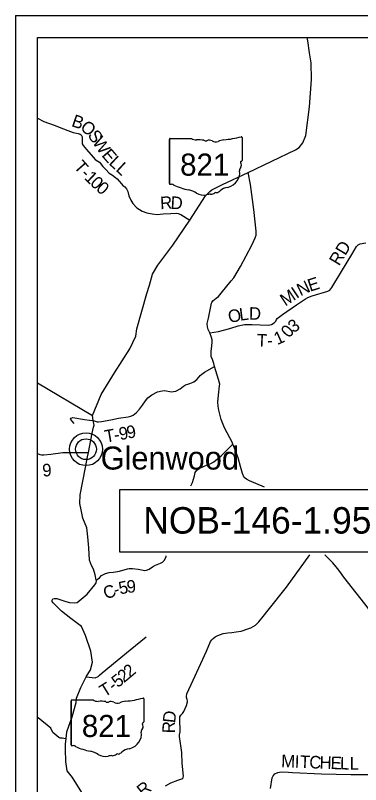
# Model space of a CAD drawing. Extents: x -15 to 405, y -40 to 87.
# Drawn here: x -7.868 to -6.302, y 17.574 to 21.058 of the extents above; entities that cross this region are included whole.
import ezdxf

# ---------------------------------------------------------------- set-up
doc = ezdxf.new("R2010")
doc.units = 0
for name, color, linetype in [('GM_P_State_Location', 7, 'Continuous'), ('GM_X_Adjacent_County', 7, 'Continuous'), ('GM_X_Major_Lake_Text', 7, 'Continuous'), ('GM_X_Minor_Lake', 7, 'Continuous'), ('GM_X_Minor_River', 7, 'Continuous'), ('GM_X_Township', 7, 'Continuous'), ('GM_X_Township_ROW', 7, 'Continuous'), ('GM_X_Township_Subdivision', 7, 'Continuous'), ('GM_X_Township_Subdivision_Text', 7, 'Continuous'), ('GM_X_Township_Text', 7, 'Continuous'), ('GM_X_Unincorporated_Location', 7, 'Continuous')]:
    doc.layers.add(name, color=color, linetype=linetype)

msp = doc.modelspace()

# ---------------------------------------------------------------- linework, layer by layer
at = {"layer": 'GM_P_State_Location'}
for points in [[(-7.6453, 20.5423), (-7.6416, 20.5409), (-7.6058, 20.5284), (-7.5836, 20.5229), (-7.5738, 20.5197), (-7.5689, 20.517), (-7.5648, 20.5087), (-7.5643, 20.4848), (-7.5644, 20.4764), (-7.5603, 20.4692), (-7.5457, 20.4505), (-7.5155, 20.4153), (-7.5057, 20.4057), (-7.4937, 20.398), (-7.487, 20.3934), (-7.481, 20.3873), (-7.4716, 20.3743), (-7.4574, 20.3594), (-7.4421, 20.3437), (-7.4278, 20.3341), (-7.4132, 20.3245), (-7.4064, 20.3183), (-7.3971, 20.3076), (-7.3866, 20.295), (-7.3799, 20.2881), (-7.3709, 20.2809), (-7.3642, 20.2721), (-7.3583, 20.2599), (-7.3528, 20.2412), (-7.3435, 20.2211), (-7.3357, 20.2062), (-7.3167, 20.1871), (-7.293, 20.1721), (-7.2723, 20.1639), (-7.2481, 20.1587), (-7.224, 20.157), (-7.1979, 20.159), (-7.1627, 20.1602), (-7.137, 20.1618), (-7.1294, 20.161), (-7.1177, 20.1567), (-7.0772, 20.1302)], [(-6.9855, 19.6208), (-6.947, 19.6268), (-6.8954, 19.6405), (-6.8575, 19.6512), (-6.8287, 19.6573), (-6.8166, 19.6584), (-6.7939, 19.6585), (-6.7217, 19.6548), (-6.7062, 19.6584), (-6.6933, 19.6659), (-6.6868, 19.6734), (-6.684, 19.6802), (-6.6802, 19.6855), (-6.6684, 19.6941), (-6.6554, 19.7038), (-6.5926, 19.7464), (-6.5519, 19.7741), (-6.5413, 19.7801), (-6.5208, 19.7871), (-6.4506, 19.8091), (-6.4415, 19.8132), (-6.4323, 19.8249), (-6.3881, 19.898), (-6.3412, 19.9756), (-6.3204, 20.0107), (-6.3136, 20.0186), (-6.3033, 20.023), (-6.2775, 20.0285)], [(-7.5144, 19.2228), (-7.4968, 19.2174), (-7.4912, 19.2175), (-7.4775, 19.2183), (-7.4348, 19.2262), (-7.3997, 19.2333), (-7.3558, 19.2401), (-7.3448, 19.2421), (-7.3339, 19.2468), (-7.3177, 19.2598), (-7.3045, 19.2743), (-7.291, 19.2919), (-7.2779, 19.3128), (-7.2667, 19.3262), (-7.2486, 19.3392), (-7.2229, 19.3523), (-7.2014, 19.3582), (-7.1916, 19.359), (-7.1601, 19.3536), (-7.1506, 19.354), (-7.1393, 19.3556), (-7.1208, 19.3668), (-7.105, 19.3783), (-7.0959, 19.3841), (-7.0857, 19.3872), (-7.0718, 19.3922), (-7.0586, 19.398), (-7.0442, 19.4084), (-7.0345, 19.4206), (-7.0289, 19.4274), (-7.0228, 19.4332), (-7.0093, 19.4416), (-6.9644, 19.4682)], [(-7.6014, 19.2096), (-7.6174, 19.2293), (-7.6141, 19.2334), (-7.6075, 19.2363), (-7.5538, 19.228), (-7.5321, 19.2252), (-7.5144, 19.2228)], [(-7.7679, 19.0738), (-7.7563, 19.0694), (-7.7495, 19.0675), (-7.7381, 19.0672), (-7.7075, 19.0701), (-7.6522, 19.0785), (-7.6231, 19.0787), (-7.5369, 19.0787)], [(-7.1873, 17.5685), (-7.1632, 17.5812), (-7.1311, 17.5944), (-7.113, 17.6006), (-7.1088, 17.6025), (-7.1062, 17.6052), (-7.1055, 17.6113), (-7.1112, 17.6712), (-7.1134, 17.7189), (-7.123, 17.7909), (-7.1234, 17.7993), (-7.1209, 17.8129), (-7.1202, 17.8243), (-7.1212, 17.86), (-7.1221, 17.8763), (-7.1214, 17.8812), (-7.1173, 17.8884), (-7.1101, 17.8957), (-7.1041, 17.9049), (-7.0918, 17.9319), (-7.0874, 17.9482), (-7.0874, 17.9528), (-7.089, 17.9588), (-7.0921, 17.9679), (-7.0921, 17.9732), (-7.0903, 17.9842), (-7.0608, 18.0467), (-7.0012, 18.1784), (-6.9825, 18.2214), (-6.9773, 18.2294), (-6.9713, 18.2363), (-6.9615, 18.2435), (-6.9494, 18.2493), (-6.9252, 18.2586), (-6.9044, 18.2618), (-6.8863, 18.2631), (-6.867, 18.2652), (-6.8439, 18.2688), (-6.8133, 18.2789), (-6.7994, 18.2843), (-6.779, 18.2966), (-6.7628, 18.3107), (-6.7433, 18.3359), (-6.7208, 18.3638), (-6.6378, 18.4684), (-6.5326, 18.6142)], [(-7.4864, 18.0688), (-7.4748, 18.0793), (-7.4064, 18.1358), (-7.3467, 18.184), (-7.2747, 18.2424)], [(-7.5461, 18.0614), (-7.5056, 18.0576), (-7.4923, 18.0634), (-7.4864, 18.0688)], [(-7.6378, 17.7811), (-7.6483, 17.7829), (-7.6545, 17.7835), (-7.6644, 17.7848), (-7.6708, 17.7877), (-7.6986, 17.8103), (-7.7063, 17.8292), (-7.764, 17.8757), (-7.7679, 17.8783)], [(-6.7106, 17.556), (-6.703, 17.6042), (-6.6985, 17.6141), (-6.6902, 17.6226), (-6.6774, 17.628), (-6.6615, 17.6311), (-6.6289, 17.6299), (-6.6107, 17.6289), (-6.4793, 17.6231), (-6.3457, 17.6188), (-6.2389, 17.6197), (-6.2279, 17.6205), (-6.2151, 17.6225), (-6.2026, 17.6207), (-6.1847, 17.6159), (-6.1404, 17.608), (-6.09, 17.6095)]]:
    msp.add_lwpolyline(points, dxfattribs=at)
at = {"layer": 'GM_X_Adjacent_County'}
msp.add_lwpolyline([(-7.3948, 18.6284), (-6.1448, 18.6284), (-6.1448, 18.9084), (-7.3948, 18.9084)], close=True, dxfattribs=at)
at = {"layer": 'GM_X_Major_Lake_Text'}
msp.add_lwpolyline([(-7.7679, 20.5924), (-7.7387, 20.5782), (-7.6921, 20.5603), (-7.6495, 20.5439), (-7.6453, 20.5423)], dxfattribs=at)
at = {"layer": 'GM_X_Township'}
for p, q in [((-7.8679, 21.0583), (-7.8679, 14.0583)), ((-7.8679, 21.0583), (-0.8679, 21.0583)), ((-7.7679, 20.9583), (-5.4362, 20.9583)), ((-7.7679, 14.1583), (-7.7679, 20.9583))]:
    msp.add_line(p, q, dxfattribs=at)
at = {"layer": 'GM_X_Township_Subdivision'}
for p, q in [((-7.1693, 20.4967), (-7.1693, 20.2966)), ((-7.1693, 20.2966), (-7.1693, 20.4967)), ((-7.1693, 20.2966), (-7.1693, 20.4967)), ((-7.1661, 20.5002), (-7.0696, 20.5002)), ((-6.8398, 20.5051), (-6.8398, 20.4004)), ((-6.8398, 20.4005), (-6.8398, 20.4004)), ((-7.6152, 17.9538), (-7.6152, 17.7536)), ((-7.6152, 17.7536), (-7.6152, 17.9538)), ((-7.6152, 17.7536), (-7.6152, 17.9538)), ((-7.6119, 17.9572), (-7.5154, 17.9572)), ((-7.2856, 17.9622), (-7.2856, 17.8575)), ((-7.2856, 17.8575), (-7.2856, 17.8575))]:
    msp.add_line(p, q, dxfattribs=at)
for centre, major_axis, start_param, end_param in [((-7.1656, 20.4972), (0.00382, 0), 1.712693, 3.28349), ((-7.0466, 20.5234), (0.037, 0), 4.042523, 4.731795), ((-7.0343, 20.3878), (0.133, 0), 1.404758, 1.657858), ((-7.0041, 20.4982), (0.0107, 0), 3.836095, 5.185415), ((-6.9884, 20.4751), (0.0222, 0), 0.950623, 2.079405), ((-6.9126, 20.439), (0.0703, 0), 1.699011, 2.107814), ((-6.9572, 20.773), (0.3495, 0), 4.814394, 5.042369), ((-6.8434, 20.5056), (0.00367, 0), 6.141152, 7.989035), ((-6.9598, 20.5068), (0.0267, 0), 4.081561, 5.145723), ((-6.8406, 20.3928), (0.00568, 0), 1.883978, 3.671073), ((-6.8767, 20.3795), (0.0341, 0), 5.934695, 6.695948), ((-6.8437, 20.4), (0.00393, 0), 5.05454, 6.418171), ((-6.9376, 20.3433), (0.0874, 0), 5.101752, 6.440018), ((-6.8266, 20.3566), (0.0248, 0), 2.387724, 3.262537), ((-7.1655, 20.2962), (0.00385, 0), 3.00124, 4.508301), ((-7.1649, 20.3166), (0.0294, 0), 4.665946, 4.897461), ((-7.1589, 20.2851), (0.0106, 0), 0.519207, 1.627899), ((-7.0251, 20.4649), (0.2524, 0), 4.195997, 4.488961), ((-7.1004, 20.2067), (0.079, 0), 0.823519, 1.323587), ((-7.0149, 20.2841), (0.0501, 0), 4.026481, 4.996735), ((-6.986, 20.2149), (0.0412, 0), 1.495662, 1.94098), ((-6.9823, 20.2691), (0.0267, 0), 4.691044, 5.507374), ((-6.9582, 20.2497), (0.00752, 0), 1.147584, 2.315152), ((-6.9614, 20.2772), (0.0282, 0), 4.937069, 5.64225), ((-6.9007, 20.2404), (0.0479, 0), 1.647645, 2.488434), ((-7.6114, 17.9542), (0.00382, 0), 1.712693, 3.28349), ((-7.4924, 17.9804), (0.037, 0), 4.042523, 4.731795), ((-7.4801, 17.8449), (0.133, 0), 1.404758, 1.657858), ((-7.4499, 17.9552), (0.0107, 0), 3.836095, 5.185415), ((-7.4343, 17.9321), (0.0222, 0), 0.950623, 2.079405), ((-7.4056, 17.9638), (0.0267, 0), 4.081561, 5.145723), ((-7.3584, 17.8961), (0.0703, 0), 1.699011, 2.107814), ((-7.403, 18.23), (0.3495, 0), 4.814394, 5.042369), ((-7.2892, 17.9626), (0.00367, 0), 6.141152, 7.989035), ((-7.2864, 17.8498), (0.00568, 0), 1.883978, 3.671073), ((-7.3226, 17.8366), (0.0341, 0), 5.934695, 6.695948), ((-7.2895, 17.8571), (0.00393, 0), 5.05454, 6.418171), ((-7.3834, 17.8004), (0.0874, 0), 5.101752, 6.440018), ((-7.2724, 17.8137), (0.0248, 0), 2.387724, 3.262537), ((-7.6114, 17.7532), (0.00385, 0), 3.00124, 4.508301), ((-7.6108, 17.7737), (0.0294, 0), 4.665946, 4.897461), ((-7.6048, 17.7421), (0.0106, 0), 0.519207, 1.627899), ((-7.4709, 17.9219), (0.2524, 0), 4.195997, 4.488961), ((-7.5462, 17.6637), (0.079, 0), 0.823519, 1.323587), ((-7.4608, 17.7411), (0.0501, 0), 4.026481, 4.996735), ((-7.4318, 17.6719), (0.0412, 0), 1.495662, 1.94098), ((-7.4282, 17.7261), (0.0267, 0), 4.691044, 5.507374), ((-7.404, 17.7067), (0.00752, 0), 1.147584, 2.315152), ((-7.4072, 17.7343), (0.0282, 0), 4.937069, 5.64225), ((-7.3465, 17.6975), (0.0479, 0), 1.647645, 2.488434)]:
    msp.add_ellipse(centre, major_axis=major_axis, ratio=0.8, start_param=start_param, end_param=end_param, dxfattribs=at)
at = {"layer": 'GM_X_Township_Subdivision_Text'}
for radius in [0.0744, 0.0472]:
    msp.add_circle((-7.5475, 19.093), radius, dxfattribs=at)
at = {"layer": 'GM_X_Township_Text'}
for points in [[(-6.8817, 19.1161), (-6.884, 19.1244), (-6.8951, 19.1445), (-6.9185, 19.1905), (-6.9339, 19.228), (-6.9445, 19.27), (-6.948, 19.2874), (-6.9496, 19.3063), (-6.9468, 19.3386), (-6.9414, 19.3796), (-6.9411, 19.3879), (-6.9462, 19.4095), (-6.9644, 19.4682), (-6.9679, 19.4814), (-6.9741, 19.4992), (-6.9795, 19.5136), (-6.9799, 19.5242), (-6.9796, 19.5352), (-6.9764, 19.5617), (-6.9746, 19.5781), (-6.9755, 19.5887), (-6.9778, 19.5997), (-6.9855, 19.6208), (-6.9936, 19.6356), (-6.9959, 19.6472), (-6.998, 19.6624), (-6.9921, 19.6873), (-6.9778, 19.7543), (-6.9762, 19.7584), (-6.972, 19.7649), (-6.9651, 19.7712), (-6.9567, 19.7772), (-6.9472, 19.7843), (-6.9346, 19.8005), (-6.8883, 19.8558), (-6.8772, 19.8693), (-6.8464, 19.921), (-6.7959, 20.0172), (-6.7797, 20.0504), (-6.7762, 20.0628), (-6.776, 20.0803), (-6.7864, 20.179), (-6.8019, 20.2917), (-6.812, 20.3473)], [(-7.0717, 18.9274), (-7.0645, 18.9425), (-7.0556, 18.9729), (-7.0523, 18.9869), (-7.0451, 18.9976), (-7.0342, 19.0064), (-7.0116, 19.0157), (-6.9806, 19.0289), (-6.9682, 19.0358), (-6.9351, 19.0637), (-6.8817, 19.1161)], [(-6.7373, 18.9206), (-6.8063, 18.9495), (-6.8188, 18.9566), (-6.8299, 18.9656), (-6.838, 18.9826), (-6.8461, 19.0151), (-6.8578, 19.0541), (-6.874, 19.098), (-6.8817, 19.1161)], [(-7.5007, 18.5004), (-7.487, 18.5109), (-7.4768, 18.5205), (-7.4715, 18.5247), (-7.4598, 18.5293), (-7.4425, 18.534), (-7.4247, 18.5353), (-7.4141, 18.5369), (-7.3956, 18.5405), (-7.36, 18.5514), (-7.3517, 18.553), (-7.337, 18.5531), (-7.3104, 18.5499), (-7.2884, 18.5447), (-7.2805, 18.544), (-7.2729, 18.5449), (-7.2612, 18.5499), (-7.2465, 18.5595), (-7.2318, 18.5679), (-7.2099, 18.5765), (-7.2005, 18.5811), (-7.1911, 18.5903), (-7.184, 18.6074), (-7.1836, 18.6093)], [(-5.8501, 18.0766), (-5.8502, 18.0767), (-5.8522, 18.0813), (-5.853, 18.0862), (-5.8516, 18.1063), (-5.8675, 18.1077), (-5.9948, 18.1157), (-6.0455, 18.1188), (-6.0615, 18.1229), (-6.0728, 18.1281), (-6.0923, 18.1462), (-6.1565, 18.2272), (-6.2164, 18.3048), (-6.2829, 18.3919), (-6.3616, 18.4918), (-6.3819, 18.5193), (-6.3922, 18.5329), (-6.406, 18.5521), (-6.4274, 18.5781), (-6.4635, 18.6152)]]:
    msp.add_lwpolyline(points, dxfattribs=at)
at = {"layer": 'GM_X_Unincorporated_Location'}
msp.add_line((-7.7679, 19.393), (-7.5179, 19.2452), dxfattribs=at)
for points in [[(-7.5179, 19.2452), (-7.4787, 19.3411), (-7.4177, 19.4394), (-7.3494, 19.5475), (-7.3219, 19.605), (-7.3167, 19.6377), (-7.2714, 19.7984), (-7.2602, 19.8368), (-7.2459, 19.8857), (-7.2217, 19.9267), (-7.1534, 20.0177), (-7.0772, 20.1302), (-7.0061, 20.2413), (-6.9855, 20.2612), (-6.976, 20.2687), (-6.9289, 20.2922), (-6.812, 20.3473), (-6.5972, 20.4486), (-6.5807, 20.4598), (-6.5635, 20.4809), (-6.5507, 20.514), (-6.5338, 20.6441), (-6.5252, 20.7676), (-6.5267, 20.844), (-6.5329, 20.8891), (-6.5405, 20.9436), (-6.5436, 20.9583)], [(-7.5659, 17.5381), (-7.6084, 17.6066), (-7.6332, 17.6357), (-7.6394, 17.6782), (-7.6404, 17.7325), (-7.6399, 17.7587), (-7.6378, 17.7811), (-7.635, 17.8122), (-7.611, 17.8807), (-7.5926, 17.9449), (-7.59, 17.9653), (-7.5709, 18.0137), (-7.5461, 18.0614), (-7.5268, 18.0933), (-7.5186, 18.129), (-7.526, 18.1776), (-7.5501, 18.2492), (-7.5685, 18.2905), (-7.6161, 18.3267), (-7.6587, 18.3588), (-7.6834, 18.383), (-7.6968, 18.3966), (-7.7013, 18.4027), (-7.7017, 18.4087), (-7.6976, 18.4148), (-7.6919, 18.4172), (-7.6798, 18.4168), (-7.6384, 18.4037), (-7.6224, 18.3981), (-7.5986, 18.397), (-7.5873, 18.3986), (-7.5422, 18.4358), (-7.5072, 18.4782), (-7.502, 18.4881), (-7.5001, 18.4972), (-7.5007, 18.5004), (-7.5053, 18.5239), (-7.5137, 18.5501), (-7.5229, 18.5668), (-7.5313, 18.5906), (-7.5349, 18.6457), (-7.5397, 18.6965), (-7.5417, 18.7227), (-7.5436, 18.7368), (-7.5616, 18.7803), (-7.5701, 18.8179), (-7.5755, 18.8471), (-7.5738, 18.8858), (-7.5496, 19.0105), (-7.541, 19.0583), (-7.5369, 19.0787), (-7.5191, 19.1651), (-7.5133, 19.1927), (-7.5112, 19.2027), (-7.5144, 19.2228), (-7.5179, 19.2452)]]:
    msp.add_lwpolyline(points, dxfattribs=at)

# ---------------------------------------------------------------- texts
at = {"layer": 'GM_X_Minor_Lake'}
for s, rotation, p in [('C', 21.1349, (-7.4566, 18.4114)), ('5', 11.5896, (-7.3933, 18.4347)), ('9', 5.2261, (-7.3606, 18.4415)), ('-', 17.9532, (-7.4139, 18.4279))]:
    msp.add_text(s, height=0.0568, rotation=rotation, dxfattribs=at).set_placement(p)
at = {"layer": 'GM_X_Minor_River'}
for s, height, rotation, p in [('B', 0.0568, 341.1824, (-7.6168, 20.5574)), ('O', 0.0568, 319.652, (-7.5775, 20.5451)), ('S', 0.0568, 303.7981, (-7.5422, 20.5158)), ('W', 0.0568, 304.1143, (-7.5206, 20.4837)), ('E', 0.0568, 310.8394, (-7.4793, 20.4234)), ('L', 0.0568, 316.7332, (-7.4471, 20.3866)), ('T', 0.0568, 311.7407, (-7.6061, 20.3705)), ('L', 0.0568, 317.2275, (-7.4157, 20.3571)), ('-', 0.0568, 315.4272, (-7.5751, 20.3359)), ('1', 0.0568, 315.6579, (-7.5583, 20.3194)), ('0', 0.0568, 316.6269, (-7.5325, 20.2942)), ('0', 0.0568, 318.7464, (-7.5054, 20.2686)), ('R', 0.0568, 2.9207, (-7.21, 20.18)), ('D', 0.0568, 356.6686, (-7.165, 20.1824)), ('RD', 0.05682, 58.8678, (-6.3996, 19.9204)), ('E', 0.0568, 18.0162, (-6.5312, 19.8059)), ('I', 0.0568, 33.6836, (-6.5921, 19.7733)), ('N', 0.0568, 25.4099, (-6.5745, 19.7852)), ('M', 0.0568, 33.9563, (-6.6431, 19.7389)), ('O', 0.0568, 13.5123, (-6.8958, 19.6635)), ('L', 0.0568, 7.1543, (-6.8488, 19.6749)), ('D', 0.0568, 358.5501, (-6.8089, 19.6801)), ('0', 0.0568, 48.1782, (-6.627, 19.5937)), ('3', 0.0568, 35.4282, (-6.6062, 19.6176)), ('1', 0.0568, 24.044, (-6.6799, 19.5642)), ('T', 0.0568, 357.4192, (-6.7737, 19.5592)), ('-', 0.0568, 4.0323, (-6.7241, 19.5573)), ('9', 0.0568, 11.1034, (-7.3578, 19.1402)), ('T', 0.0568, 10.0196, (-7.4582, 19.1223)), ('9', 0.0568, 10.2711, (-7.3931, 19.1338)), ('-', 0.0568, 10.0564, (-7.4163, 19.1297)), ('9', 0.0568, 3.9219, (-7.7438, 18.9687)), ('2', 0.0568, 39.9316, (-7.3754, 18.0327)), ('2', 0.0568, 40.0855, (-7.3484, 18.0552)), ('5', 0.0568, 39.4328, (-7.4028, 18.0101)), ('T', 0.0568, 31.87, (-7.4638, 17.9683)), ('-', 0.0568, 38.7111, (-7.4216, 17.995)), ('D', 0.0568, 83.9418, (-7.1433, 17.851)), ('R', 0.0568, 88.5909, (-7.1444, 17.8056)), ('M', 0.0568, 357.8996, (-6.6629, 17.6526)), ('I', 0.0568, 357.8964, (-6.6013, 17.6503)), ('T', 0.0568, 357.8987, (-6.578, 17.6495)), ('C', 0.0568, 357.8997, (-6.5355, 17.6479)), ('H', 0.0568, 357.8976, (-6.4889, 17.6462)), ('E', 0.0568, 357.9068, (-6.4389, 17.6444)), ('L', 0.0568, 358.331, (-6.396, 17.6428)), ('L', 0.0568, 0.2264, (-6.3514, 17.6416)), ('R', 0.0568, 38.8205, (-7.2885, 17.5158))]:
    msp.add_text(s, height=height, rotation=rotation, dxfattribs=at).set_placement(p)
at = {"layer": 'GM_X_Township'}
msp.add_text('NOB-146-1.95', height=0.12, dxfattribs=at).set_placement((-7.2875, 18.7107))
at = {"layer": 'GM_X_Township_ROW'}
msp.add_text('Glenwood', height=0.10417, rotation=0, dxfattribs=at).set_placement((-7.481, 19.0009))
at = {"layer": 'GM_X_Township_Subdivision'}
for p in [(-7.1205, 20.3323), (-7.5664, 17.7894)]:
    msp.add_text('821', height=0.1, dxfattribs=at).set_placement(p)

doc.saveas('drawing.dxf')
